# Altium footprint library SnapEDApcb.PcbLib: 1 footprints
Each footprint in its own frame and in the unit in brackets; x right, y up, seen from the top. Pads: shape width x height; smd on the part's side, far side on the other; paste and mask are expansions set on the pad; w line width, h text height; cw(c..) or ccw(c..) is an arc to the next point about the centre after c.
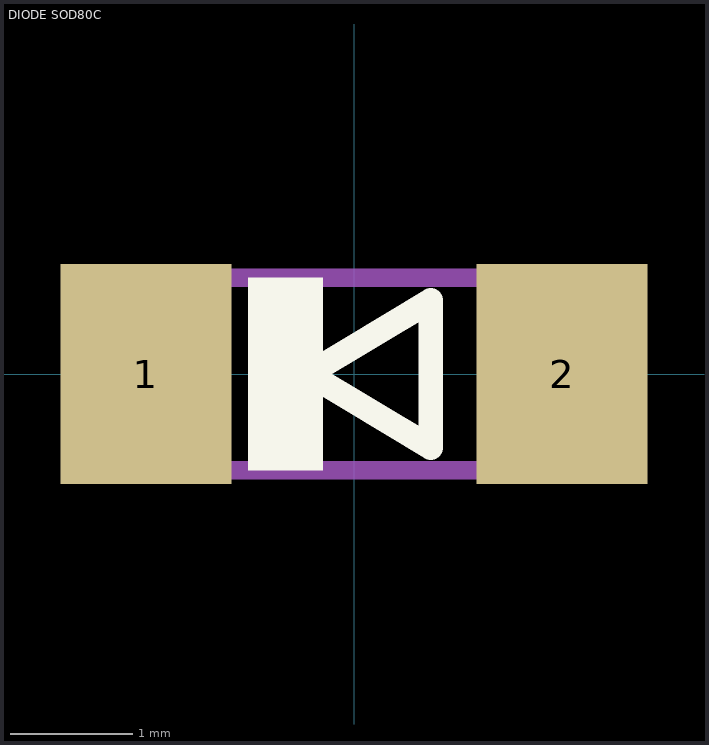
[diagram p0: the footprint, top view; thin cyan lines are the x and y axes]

## DIODE SOD80C [mm] "Diode Standard 75V 200mA _DC_ Surface Mount LLDS; MiniMelf DIODE SOD80C PMLL4148L"
pads (2):
  rect 1.4x1.8 smd: 1(-1.7,0) 2(1.7,0)
Top Overlay:
  region: -0.254,-0.788 -0.864,-0.788 -0.864,0.787 -0.254,0.787
  lines w0.203: -0.373,0 0.627,-0.6 0.627,0.6 -0.373,0
Mechanical 13:
  region: 1.854,-0.865 1.298,-0.865 1.298,0.864 1.854,0.864
  region: -1.295,-0.865 -1.857,-0.865 -1.857,0.864 -1.295,0.864
  lines w0.152: -1.321,-0.787 1.321,-0.787 ; -1.321,0.787 1.321,0.787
